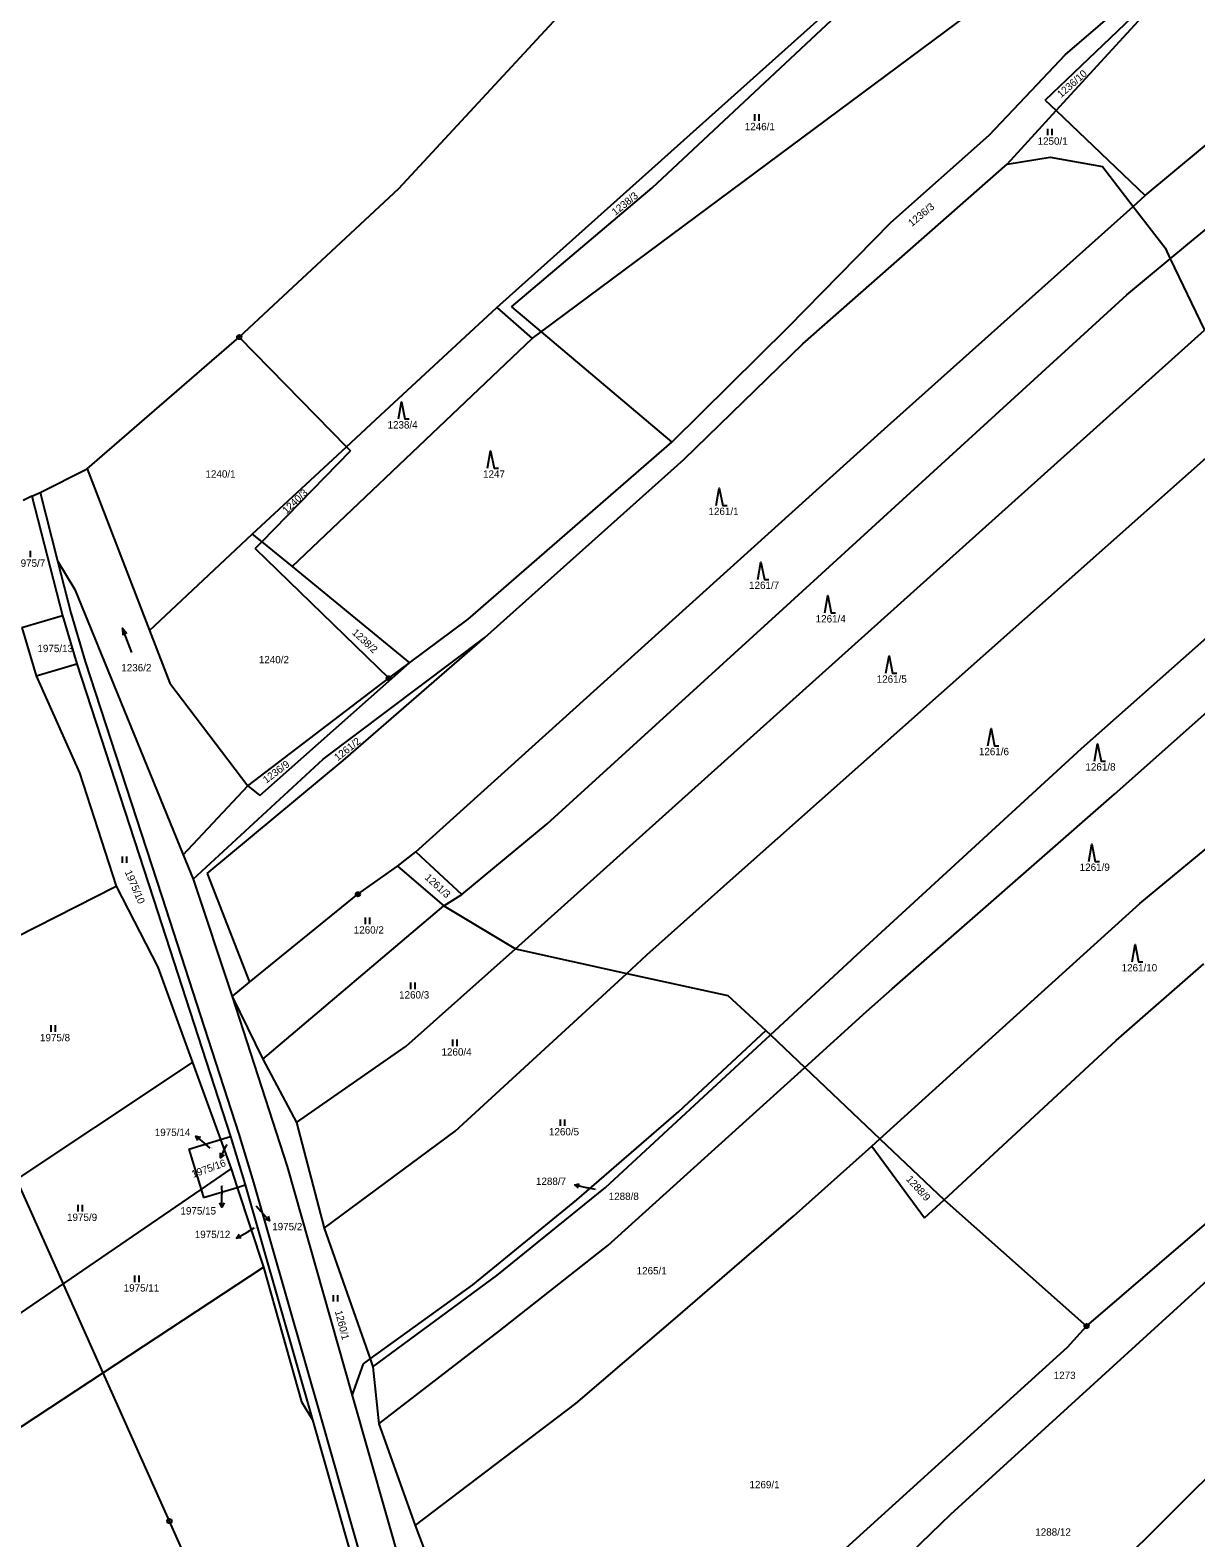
# Model space of a CAD drawing. Extents: x -763205 to -760228, y -1155311 to -1152844.
# Drawn here: x -761366.2 to -761096.9, y -1154305.4 to -1153957 of the extents above; entities that cross this region are included whole.
import ezdxf

# ---------------------------------------------------------------- set-up
doc = ezdxf.new("R2010")
doc.units = 0
for name, color, linetype in [('Vrstva 1', 7, 'Continuous'), ('Vrstva 12', 7, 'Continuous'), ('Vrstva 13', 7, 'Continuous'), ('Vrstva 16', 7, 'Continuous'), ('Vrstva 18', 7, 'Continuous'), ('Vrstva 24', 7, 'Continuous'), ('Vrstva 25', 7, 'Continuous'), ('Vrstva 26', 7, 'Continuous'), ('Vrstva 6', 7, 'Continuous')]:
    doc.layers.add(name, color=color, linetype=linetype)

msp = doc.modelspace()

# ---------------------------------------------------------------- linework, layer by layer
at = {"layer": 'Vrstva 1'}
for p, q in [((-761222.52, -1153993.4), (-761162.03, -1153936.88)), ((-761129.15, -1153975.6), (-761104.94, -1153949.11)), ((-761127.05, -1153962.67), (-761107.88, -1153946.17)), ((-761134.87, -1153970.95), (-761127.05, -1153962.67)), ((-761144.62, -1153981.27), (-761134.87, -1153970.95)), ((-761140.48, -1153988), (-761129.15, -1153975.6)), ((-761167.31, -1154001.41), (-761144.62, -1153981.27)), ((-761140.48, -1153988), (-761130.53, -1153986.31)), ((-761130.53, -1153986.31), (-761118.45, -1153988.53)), ((-761187.71, -1154029.48), (-761140.48, -1153988)), ((-761118.45, -1153988.53), (-761111.37, -1153997.72)), ((-761254.97, -1154020.92), (-761222.52, -1153993.4)), ((-761111.37, -1153997.72), (-761103.97, -1154007.33)), ((-761191.06, -1154025.62), (-761167.31, -1154001.41)), ((-761103.97, -1154007.33), (-761102.76, -1154009.86)), ((-761102.76, -1154009.86), (-761094.88, -1154026.35)), ((-761254.97, -1154020.92), (-761248.12, -1154026.72)), ((-761217.96, -1154052.24), (-761191.06, -1154025.62)), ((-761317.89, -1154027.92), (-761293.12, -1154053.26)), ((-761248.12, -1154026.72), (-761217.96, -1154052.24)), ((-761215.2, -1154056.2), (-761187.71, -1154029.48)), ((-761293.12, -1154053.26), (-761292.2, -1154054.2)), ((-761264.97, -1154093.08), (-761217.96, -1154052.24)), ((-761312.7, -1154075.27), (-761292.2, -1154054.2)), ((-761261.18, -1154097.32), (-761215.2, -1154056.2)), ((-761353.03, -1154058.4), (-761338.65, -1154095.7)), ((-761363.9, -1154063.8), (-761359.89, -1154079.59)), ((-761365.8, -1154064.7), (-761358.73, -1154092.24)), ((-761314.2, -1154076.81), (-761312.7, -1154075.27)), ((-761314.2, -1154076.81), (-761283.35, -1154106.76)), ((-761359.89, -1154079.59), (-761355.9, -1154086.28)), ((-761359.89, -1154079.59), (-761356.82, -1154091.68)), ((-761355.9, -1154086.28), (-761330.87, -1154147.53)), ((-761368.13, -1154095.01), (-761358.73, -1154092.24)), ((-761358.73, -1154092.24), (-761355.43, -1154103.46)), ((-761356.82, -1154091.68), (-761353.51, -1154102.9)), ((-761368.13, -1154095.01), (-761364.83, -1154106.23)), ((-761338.65, -1154095.7), (-761333.94, -1154107.91)), ((-761278.54, -1154103.18), (-761264.97, -1154093.08)), ((-761298.54, -1154125.43), (-761261.18, -1154097.32)), ((-761364.83, -1154106.23), (-761355.43, -1154103.46)), ((-761355.43, -1154103.46), (-761337.71, -1154157.8)), ((-761353.51, -1154102.9), (-761335.81, -1154157.18)), ((-761283.35, -1154106.76), (-761278.54, -1154103.18)), ((-761333.94, -1154107.91), (-761315.9, -1154131.65)), ((-761315.9, -1154131.65), (-761283.35, -1154106.76)), ((-761328.54, -1154153.22), (-761298.54, -1154125.43)), ((-761330.87, -1154147.53), (-761315.9, -1154131.65)), ((-761330.87, -1154147.53), (-761328.54, -1154153.22)), ((-761290.49, -1154156.66), (-761281.37, -1154150.2)), ((-761281.37, -1154150.2), (-761270.66, -1154159.38)), ((-761328.54, -1154153.22), (-761319.51, -1154180.28)), ((-761337.71, -1154157.8), (-761319.96, -1154212.66)), ((-761335.81, -1154157.18), (-761318.04, -1154212.08)), ((-761315.51, -1154177.02), (-761290.49, -1154156.66)), ((-761270.66, -1154159.38), (-761254.04, -1154169.3)), ((-761254.04, -1154169.3), (-761228.35, -1154174.95)), ((-761228.35, -1154174.95), (-761205.02, -1154180.07)), ((-761319.51, -1154180.28), (-761315.51, -1154177.02)), ((-761122.11, -1154256.47), (-761030.68, -1154177.91)), ((-761319.51, -1154180.28), (-761306.83, -1154219.62)), ((-761205.02, -1154180.07), (-761196.24, -1154188.16)), ((-761216.34, -1154206.9), (-761196.24, -1154188.16)), ((-761196.24, -1154188.16), (-761195.17, -1154189.17)), ((-761195.17, -1154189.17), (-761187.24, -1154196.69)), ((-761187.24, -1154196.69), (-761169.85, -1154213.18)), ((-761239.89, -1154227.28), (-761216.34, -1154206.9)), ((-761329.53, -1154215.56), (-761322.24, -1154213.35)), ((-761322.24, -1154213.35), (-761319.96, -1154212.66)), ((-761319.96, -1154212.66), (-761316.57, -1154223.86)), ((-761318.04, -1154212.08), (-761314.65, -1154223.28)), ((-761169.85, -1154213.18), (-761155.01, -1154227.25)), ((-761329.53, -1154215.56), (-761326.71, -1154224.89)), ((-761306.83, -1154219.62), (-761291.79, -1154272.54)), ((-761326.14, -1154226.76), (-761318.37, -1154224.41)), ((-761318.37, -1154224.41), (-761316.57, -1154223.86)), ((-761316.57, -1154223.86), (-761300.97, -1154278.14)), ((-761314.65, -1154223.28), (-761299.05, -1154277.59)), ((-761326.71, -1154224.89), (-761326.14, -1154226.76)), ((-761263.96, -1154246.96), (-761239.89, -1154227.28)), ((-761155.01, -1154227.25), (-761154.34, -1154227.89)), ((-761154.34, -1154227.89), (-761122.11, -1154256.47)), ((-761287.66, -1154264.06), (-761263.96, -1154246.96)), ((-761291.79, -1154272.54), (-761289.23, -1154265.19)), ((-761289.23, -1154265.19), (-761287.66, -1154264.06)), ((-761291.79, -1154272.54), (-761276.38, -1154326.75)), ((-761300.97, -1154278.14), (-761287.46, -1154325.75)), ((-761299.05, -1154277.59), (-761285.54, -1154325.21))]:
    msp.add_line(p, q, dxfattribs=at)
at = {"layer": 'Vrstva 12'}
for p, q in [((-761334.03, -1154301.54), (-761369.5, -1154222.09)), ((-761299.63, -1154378.29), (-761334.03, -1154301.54))]:
    msp.add_line(p, q, dxfattribs=at)
at = {"layer": 'Vrstva 13'}
for p, q in [((-761281.02, -1153993.61), (-761240.45, -1153949.68)), ((-761309.99, -1154020.57), (-761281.02, -1153993.61)), ((-761317.89, -1154027.92), (-761309.99, -1154020.57)), ((-761353.03, -1154058.4), (-761317.89, -1154027.92)), ((-761363.9, -1154063.8), (-761353.03, -1154058.4)), ((-761365.8, -1154064.7), (-761363.9, -1154063.8)), ((-761365.8, -1154064.7), (-761367.82, -1154065.65))]:
    msp.add_line(p, q, dxfattribs=at)
at = {"layer": 'Vrstva 16'}
for p, q in [((-761327.945, -1154212.548), (-761325.65, -1154214.48)), ((-761324.59, -1154215.37), (-761325.65, -1154214.48)), ((-761322.231, -1154217.547), (-761320.96, -1154214.83)), ((-761320.79, -1154214.47), (-761320.96, -1154214.83)), ((-761321.97, -1154224.04), (-761321.95, -1154225.98)), ((-761240.384, -1154223.855), (-761237.45, -1154224.48)), ((-761235.59, -1154224.87), (-761237.45, -1154224.48)), ((-761321.913, -1154228.98), (-761321.95, -1154225.98)), ((-761313.97, -1154228.64), (-761312.88, -1154229.9)), ((-761310.912, -1154232.164), (-761312.88, -1154229.9)), ((-761318.552, -1154236.126), (-761315.94, -1154234.65)), ((-761314.5, -1154233.84), (-761315.94, -1154234.65))]:
    msp.add_line(p, q, dxfattribs=at)
for points in [[(-761327.502, -1154213.574), (-761327.945, -1154212.548), (-761326.858, -1154212.809)], [(-761321.355, -1154216.853), (-761322.231, -1154217.547), (-761322.26, -1154216.43)], [(-761239.51, -1154224.553), (-761240.384, -1154223.855), (-761239.302, -1154223.574)], [(-761321.425, -1154227.974), (-761321.913, -1154228.98), (-761322.425, -1154227.986)], [(-761311.191, -1154231.082), (-761310.912, -1154232.164), (-761311.946, -1154231.738)], [(-761317.435, -1154236.069), (-761318.552, -1154236.126), (-761317.927, -1154235.198)]]:
    msp.add_lwpolyline(points, dxfattribs=at)
at = {"layer": 'Vrstva 24'}
for centre, radius in [((-761317.89, -1154027.92), 0.5), ((-761317.89, -1154027.92), 0.1), ((-761283.35, -1154106.76), 0.5), ((-761283.35, -1154106.76), 0.1), ((-761290.49, -1154156.66), 0.5), ((-761290.49, -1154156.66), 0.1), ((-761122.11, -1154256.47), 0.5), ((-761122.11, -1154256.47), 0.1)]:
    msp.add_circle(centre, radius, dxfattribs=at)
at = {"layer": 'Vrstva 25'}
for p, q in [((-761198.79, -1153977.92), (-761198.79, -1153976.42)), ((-761197.79, -1153977.92), (-761197.79, -1153976.42)), ((-761131.07, -1153981.28), (-761131.07, -1153979.78)), ((-761130.07, -1153981.28), (-761130.07, -1153979.78)), ((-761366.18, -1154078.8), (-761366.18, -1154077.3)), ((-761344.89, -1154149.43), (-761344.89, -1154147.93)), ((-761343.89, -1154149.43), (-761343.89, -1154147.93)), ((-761288.76, -1154163.57), (-761288.76, -1154162.07)), ((-761287.76, -1154163.57), (-761287.76, -1154162.07)), ((-761278.27, -1154178.57), (-761278.27, -1154177.07)), ((-761277.27, -1154178.57), (-761277.27, -1154177.07)), ((-761361.38, -1154188.45), (-761361.38, -1154186.95)), ((-761360.38, -1154188.45), (-761360.38, -1154186.95)), ((-761268.54, -1154191.76), (-761268.54, -1154190.26)), ((-761267.54, -1154191.76), (-761267.54, -1154190.26)), ((-761243.67, -1154210.19), (-761243.67, -1154208.69)), ((-761242.67, -1154210.19), (-761242.67, -1154208.69)), ((-761355.16, -1154229.97), (-761355.16, -1154228.47)), ((-761354.16, -1154229.97), (-761354.16, -1154228.47)), ((-761342.07, -1154246.29), (-761342.07, -1154244.79)), ((-761341.07, -1154246.29), (-761341.07, -1154244.79)), ((-761296.15, -1154250.82), (-761296.15, -1154249.32)), ((-761295.15, -1154250.82), (-761295.15, -1154249.32))]:
    msp.add_line(p, q, dxfattribs=at)
for points in [[(-761281.13, -1154046.85), (-761280.43, -1154042.85), (-761279.63, -1154046.85), (-761278.63, -1154046.85)], [(-761260.51, -1154058.23), (-761259.81, -1154054.23), (-761259.01, -1154058.23), (-761258.01, -1154058.23)], [(-761207.69, -1154066.84), (-761206.99, -1154062.84), (-761206.19, -1154066.84), (-761205.19, -1154066.84)], [(-761198.04, -1154083.92), (-761197.34, -1154079.92), (-761196.54, -1154083.92), (-761195.54, -1154083.92)], [(-761182.61, -1154091.67), (-761181.91, -1154087.67), (-761181.11, -1154091.67), (-761180.11, -1154091.67)], [(-761342.723, -1154100.802), (-761344.917, -1154095.218), (-761344.834, -1154096.797)], [(-761344.917, -1154095.218), (-761343.903, -1154096.431)], [(-761168.46, -1154105.6), (-761167.76, -1154101.6), (-761166.96, -1154105.6), (-761165.96, -1154105.6)], [(-761144.89, -1154122.34), (-761144.19, -1154118.34), (-761143.39, -1154122.34), (-761142.39, -1154122.34)], [(-761120.25, -1154125.89), (-761119.55, -1154121.89), (-761118.75, -1154125.89), (-761117.75, -1154125.89)], [(-761121.6, -1154149.07), (-761120.9, -1154145.07), (-761120.1, -1154149.07), (-761119.1, -1154149.07)], [(-761111.59, -1154172.31), (-761110.89, -1154168.31), (-761110.09, -1154172.31), (-761109.09, -1154172.31)]]:
    msp.add_lwpolyline(points, dxfattribs=at)
at = {"layer": 'Vrstva 26'}
msp.add_circle((-761334.03, -1154301.54), 0.5, dxfattribs=at)
at = {"layer": 'Vrstva 6'}
for p, q in [((-761131.67, -1153973.2), (-761063.1, -1153907.61)), ((-761258.41, -1154021.07), (-761181.53, -1153952.29)), ((-761248.12, -1154026.72), (-761149.23, -1153953.23)), ((-761108.53, -1153995.17), (-761062.06, -1153956.38)), ((-761131.67, -1153973.2), (-761129.15, -1153975.6)), ((-761129.15, -1153975.6), (-761108.53, -1153995.17)), ((-761168.77, -1154049.11), (-761111.37, -1153997.72)), ((-761111.37, -1153997.72), (-761108.53, -1153995.17)), ((-761098.68, -1154006.48), (-761094.38, -1154002.91)), ((-761102.76, -1154009.86), (-761098.68, -1154006.48)), ((-761112.79, -1154018.18), (-761102.76, -1154009.86)), ((-761192.22, -1154090.69), (-761112.79, -1154018.18)), ((-761285.27, -1154045.98), (-761258.41, -1154021.07)), ((-761258.41, -1154021.07), (-761250.2, -1154028.27)), ((-761305.69, -1154080.91), (-761250.2, -1154028.27)), ((-761254.04, -1154169.3), (-761094.88, -1154026.35)), ((-761250.2, -1154028.27), (-761248.12, -1154026.72)), ((-761293.12, -1154053.26), (-761285.27, -1154045.98)), ((-761277.11, -1154146.9), (-761168.77, -1154049.11)), ((-761203.04, -1154152.3), (-761084.94, -1154047.31)), ((-761314.92, -1154073.49), (-761293.12, -1154053.26)), ((-761338.65, -1154095.7), (-761314.92, -1154073.49)), ((-761314.92, -1154073.49), (-761312.7, -1154075.27)), ((-761312.7, -1154075.27), (-761305.69, -1154080.91)), ((-761305.69, -1154080.91), (-761278.54, -1154103.18)), ((-761123.25, -1154122.98), (-761073.17, -1154078.57)), ((-761246.72, -1154140.43), (-761192.22, -1154090.69)), ((-761293.93, -1154125.77), (-761261.18, -1154097.32)), ((-761313.12, -1154133.82), (-761278.54, -1154103.18)), ((-761364.83, -1154106.23), (-761354.79, -1154128.62)), ((-761109.8, -1154158.84), (-761051.83, -1154110.71)), ((-761115.69, -1154133.56), (-761093.54, -1154113.93)), ((-761176.02, -1154171.45), (-761123.25, -1154122.98)), ((-761325.33, -1154151.88), (-761293.93, -1154125.77)), ((-761354.79, -1154128.62), (-761346.38, -1154154.82)), ((-761315.9, -1154131.65), (-761313.12, -1154133.82)), ((-761167, -1154178.54), (-761115.69, -1154133.56)), ((-761266.5, -1154156.73), (-761246.72, -1154140.43)), ((-761281.37, -1154150.2), (-761277.11, -1154146.9)), ((-761277.11, -1154146.9), (-761266.5, -1154156.73)), ((-761382.49, -1154173.17), (-761346.38, -1154154.82)), ((-761346.38, -1154154.82), (-761336.69, -1154173.51)), ((-761325.33, -1154151.88), (-761315.51, -1154177.02)), ((-761223.71, -1154170.68), (-761203.04, -1154152.3)), ((-761270.66, -1154159.38), (-761266.5, -1154156.73)), ((-761312.45, -1154194.8), (-761270.66, -1154159.38)), ((-761169.85, -1154213.18), (-761109.8, -1154158.84)), ((-761279.36, -1154191.76), (-761254.04, -1154169.3)), ((-761228.35, -1154174.95), (-761223.71, -1154170.68)), ((-761195.17, -1154189.17), (-761176.34, -1154171.74)), ((-761176.34, -1154171.74), (-761176.02, -1154171.45)), ((-761336.69, -1154173.51), (-761328.69, -1154195.57)), ((-761267.99, -1154211.42), (-761228.35, -1154174.95)), ((-761115.27, -1154190.45), (-761095.03, -1154172.79)), ((-761172.96, -1154183.77), (-761167, -1154178.54)), ((-761319.51, -1154180.28), (-761312.45, -1154194.8)), ((-761187.24, -1154196.69), (-761172.96, -1154183.77)), ((-761233.31, -1154224.47), (-761195.17, -1154189.17)), ((-761304.67, -1154209.43), (-761279.36, -1154191.76)), ((-761155.01, -1154227.25), (-761115.27, -1154190.45)), ((-761384.79, -1154232.82), (-761328.69, -1154195.57)), ((-761328.69, -1154195.57), (-761322.24, -1154213.35)), ((-761312.45, -1154194.8), (-761304.67, -1154209.43)), ((-761232.72, -1154237.82), (-761187.24, -1154196.69)), ((-761304.67, -1154209.43), (-761298.32, -1154233.84)), ((-761322.24, -1154213.35), (-761319.78, -1154220.15)), ((-761298.32, -1154233.84), (-761267.99, -1154211.42)), ((-761171.75, -1154214.9), (-761169.85, -1154213.18)), ((-761189.81, -1154231.03), (-761171.75, -1154214.9)), ((-761171.75, -1154214.9), (-761159.55, -1154231.45)), ((-761326.71, -1154224.89), (-761319.78, -1154220.15)), ((-761319.78, -1154220.15), (-761318.37, -1154224.41)), ((-761318.37, -1154224.41), (-761312.27, -1154242.83)), ((-761258.41, -1154244.76), (-761233.31, -1154224.47)), ((-761381.19, -1154262.14), (-761326.71, -1154224.89)), ((-761159.55, -1154231.45), (-761155.01, -1154227.25)), ((-761217.11, -1154254.62), (-761189.81, -1154231.03)), ((-761298.32, -1154233.84), (-761287.66, -1154264.06)), ((-761153.47, -1154299.93), (-761081.66, -1154234.43)), ((-761257.74, -1154257.58), (-761232.72, -1154237.82)), ((-761378.24, -1154286.2), (-761312.27, -1154242.83)), ((-761312.27, -1154242.83), (-761303.52, -1154273.93)), ((-761287.02, -1154265.89), (-761258.41, -1154244.76)), ((-761240.09, -1154274.33), (-761217.11, -1154254.62)), ((-761285.65, -1154279.08), (-761257.74, -1154257.58)), ((-761126.48, -1154261.31), (-761122.11, -1154256.47)), ((-761178.62, -1154308.55), (-761126.48, -1154261.31)), ((-761287.66, -1154264.06), (-761287.02, -1154265.89)), ((-761287.02, -1154265.89), (-761285.65, -1154279.08)), ((-761303.52, -1154273.93), (-761300.97, -1154278.14)), ((-761277.27, -1154302.54), (-761240.09, -1154274.33)), ((-761285.65, -1154279.08), (-761277.27, -1154302.54)), ((-761161.56, -1154358.31), (-761083.04, -1154280.22)), ((-761186.86, -1154332.05), (-761153.47, -1154299.93)), ((-761277.27, -1154302.54), (-761268.59, -1154325.19))]:
    msp.add_line(p, q, dxfattribs=at)

# ---------------------------------------------------------------- texts
at = {"layer": 'Vrstva 16'}
for s, p in [('1975/14', (-761337.423, -1154212.55)), ('1288/7', (-761249.341, -1154223.85)), ('1975/15', (-761331.487, -1154230.68)), ('1975/12', (-761328.18, -1154236.13)), ('1975/2', (-761310.287, -1154234.32))]:
    msp.add_text(s, height=1.7, dxfattribs=at).set_placement(p)
msp.add_text('1975/16', height=1.7, rotation=19.93893, dxfattribs=at).set_placement((-761328.565, -1154222.241))
at = {"layer": 'Vrstva 18'}
for s, rotation, p in [('1236/10', 41.53944, (-761127.986, -1153972.73)), ('1238/3', 38.96113, (-761230.985, -1153999.923)), ('1236/3', 39.3622, (-761162.476, -1154002.481)), ('1240/3', 43.60209, (-761306.966, -1154068.889)), ('1238/2', 317.18944, (-761291.992, -1154096.387)), ('1261/2', 38.44547, (-761295.142, -1154125.966)), ('1236/9', 36.95578, (-761311.646, -1154131.144)), ('1975/10', 293.06791, (-761344.396, -1154151.521)), ('1261/3', 317.53321, (-761275.16, -1154153.005)), ('1288/9', 311.97552, (-761163.917, -1154222.602)), ('1260/1', 284.41625, (-761295.812, -1154253.07))]:
    msp.add_text(s, height=1.7, rotation=rotation, dxfattribs=at).set_placement(p)
for s, height, p in [('1246/1', 1.7, (-761201.087, -1153980.12)), ('1250/1', 1.7, (-761133.427, -1153983.48)), ('1238/4', 1.7, (-761283.637, -1154049.05)), ('1240/1', 1.7, (-761325.707, -1154060.4)), ('1247', 1.7, (-761261.567, -1154060.43)), ('1261/1', 1.7, (-761209.477, -1154069.04)), ('1975/7', 1.7, (-761369.687, -1154081)), ('1261/7', 1.7, (-761200.097, -1154086.12)), ('1261/4', 1.7, (-761184.707, -1154093.87)), ('1975/13', 1.7, (-761364.537, -1154100.72)), ('1240/2', 1.7, (-761313.377, -1154103.3)), ('1236/2', 1.7, (-761345.157, -1154105.17)), ('1261/5', 1.7, (-761170.597, -1154107.8)), ('1261/6', 1.7, (-761146.987, -1154124.54)), ('1261/8', 1.7, (-761122.367, -1154128.09)), ('1261/9', 1.7, (-761123.697, -1154151.27)), ('1260/2', 1.7, (-761291.447, -1154165.77)), ('1261/10', 1.7, (-761114.007, -1154174.51)), ('1260/3', 1.7, (-761280.967, -1154180.77)), ('1975/8', 1.7, (-761363.947, -1154190.65)), ('1260/4', 1.7, (-761271.167, -1154193.96)), ('1260/5', 1.7, (-761246.337, -1154212.39)), ('1975/14', 0.1, (-761324.567, -1154215.37)), ('1975/16', 0.1, (-761320.767, -1154214.47)), ('1975/15', 0.1, (-761321.947, -1154224.04)), ('1288/7', 0.1, (-761235.567, -1154224.87)), ('1288/8', 1.7, (-761232.527, -1154227.32)), ('1975/9', 1.7, (-761357.697, -1154232.17)), ('1975/2', 0.1, (-761313.947, -1154228.64)), ('1975/12', 0.1, (-761314.477, -1154233.84)), ('1265/1', 1.7, (-761226.077, -1154244.52)), ('1975/11', 1.7, (-761344.607, -1154248.49)), ('1273', 1.7, (-761129.697, -1154268.69)), ('1269/1', 1.7, (-761199.997, -1154293.94)), ('1288/12', 1.7, (-761133.957, -1154304.9))]:
    msp.add_text(s, height=height, dxfattribs=at).set_placement(p)

doc.saveas('drawing.dxf')
